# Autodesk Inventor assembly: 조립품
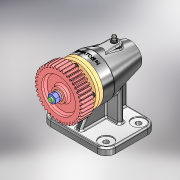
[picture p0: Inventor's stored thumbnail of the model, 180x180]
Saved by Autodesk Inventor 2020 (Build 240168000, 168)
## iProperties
Created: 2024-12
Part Number: 조립품
Document SubType Name: Assembly
Designer: shin
Author: shin
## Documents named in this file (15)
- C:\Users\shin\Desktop\741204V1020\조립품.iam
- C:\Users\shin\Desktop\741204V1020\본체.ipt
- C:\Users\shin\Desktop\741204V1020\축.ipt
- C:\Users\shin\Desktop\741204V1020\앵귤러 볼 베어링 7003A.ipt
- C:\Users\shin\Desktop\741204V1020\그리스 니플 M6x0.75.ipt
- C:\Users\shin\Desktop\741204V1020\스퍼기어.ipt
- C:\Users\shin\Desktop\741204V1020\스프링 와셔 M8.ipt
- C:\Users\shin\Desktop\741204V1020\실링.ipt
- C:\Users\shin\Desktop\741204V1020\앵귤러 볼 제어링 7204A.ipt
- C:\Users\shin\Desktop\741204V1020\오일 실 20 32 8.ipt
- C:\Users\shin\Desktop\741204V1020\육각 너트 M8.ipt
- C:\Users\shin\Desktop\741204V1020\육각 소켓 머리 볼트 M4x10.ipt
- C:\Users\shin\Desktop\741204V1020\커버.ipt
- C:\Users\shin\Desktop\741204V1020\평와셔 M8.ipt
- C:\Users\shin\Desktop\741204V1020\평행 키 4x4x14.ipt
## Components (1 placed, 1 different names)
1. 그리스 니플 M6x0.75:1
